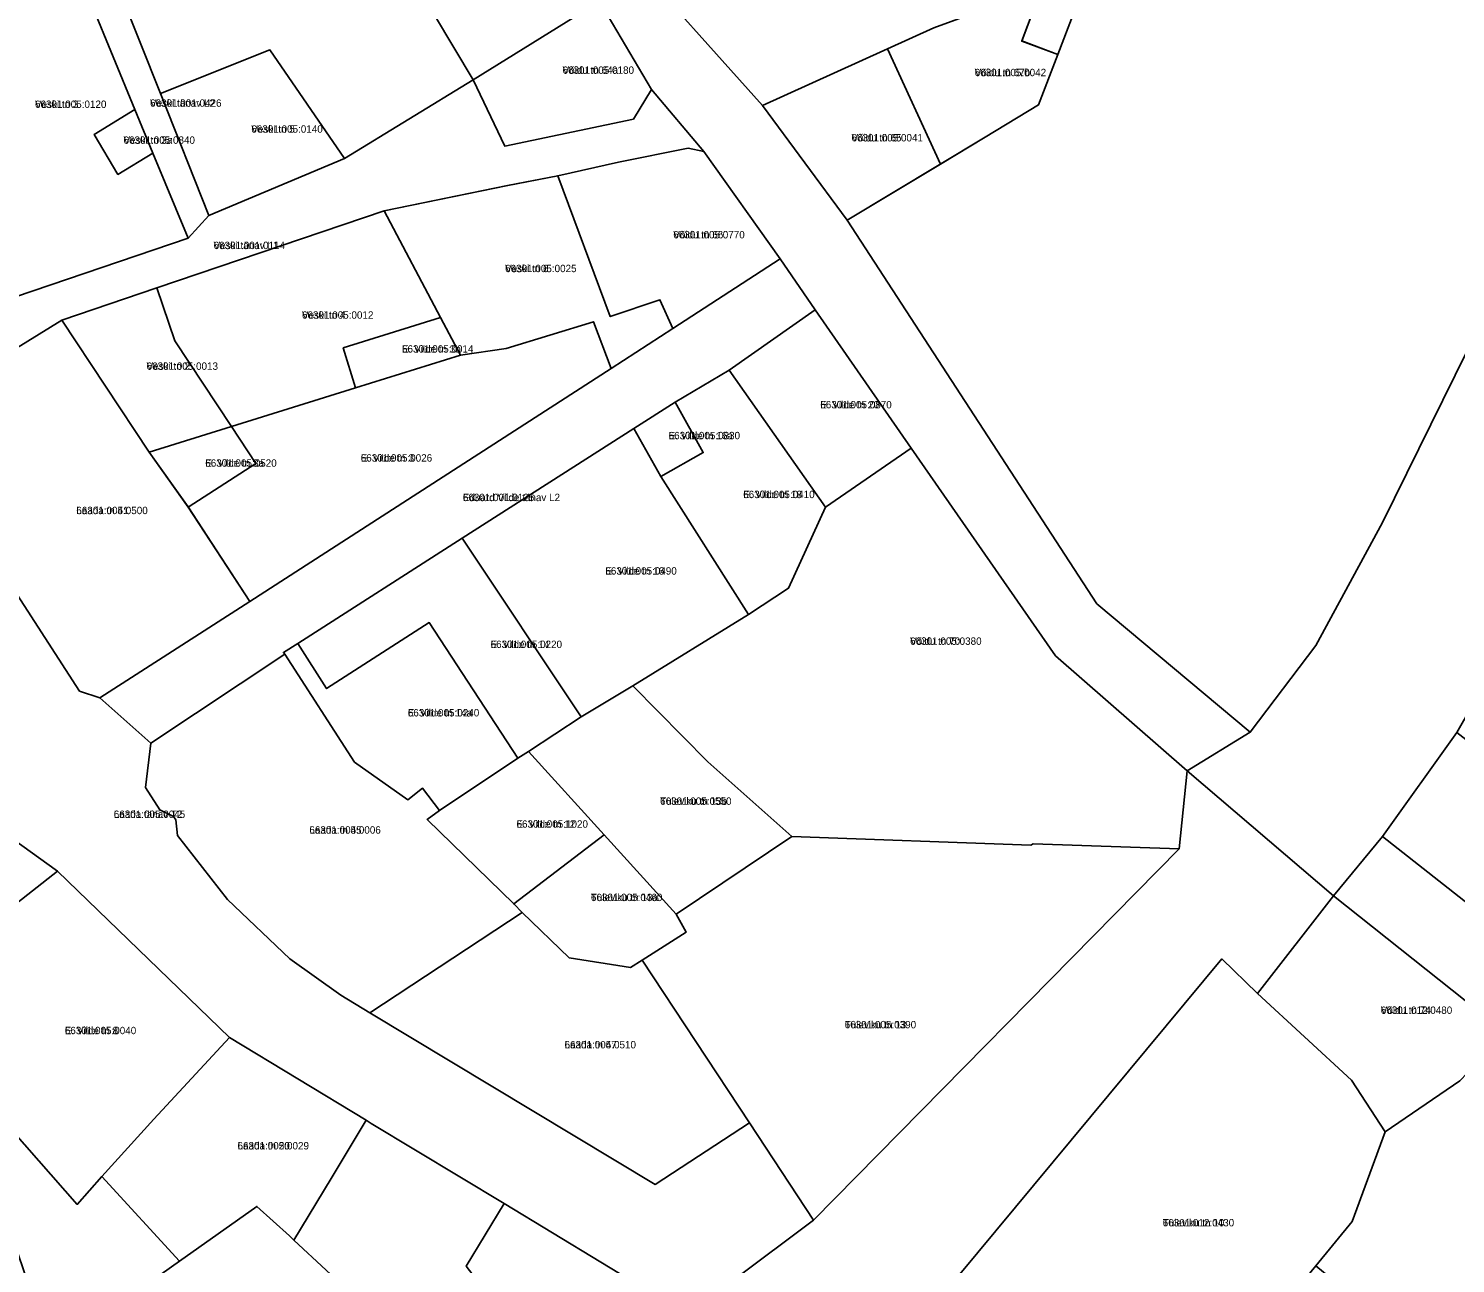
# Model space of a CAD drawing. Extents: x 632278 to 636344, y 6578401 to 6583362.
# Drawn here: x 634548.1 to 634837.7, y 6581009.9 to 6581260.6 of the extents above; entities that cross this region are included whole.
import ezdxf

# ---------------------------------------------------------------- set-up
doc = ezdxf.new("R2010")
doc.units = 0
for name, color, linetype in [('L_AADRESS', 7, 'Continuous'), ('PIIR', 7, 'Continuous'), ('TUNNUS', 7, 'Continuous')]:
    doc.layers.add(name, color=color, linetype=linetype)

msp = doc.modelspace()

# ---------------------------------------------------------------- linework, layer by layer
at = {"layer": 'PIIR'}
for points in [[(634574.9, 6581247.39), (634566.68, 6581268.15), (634584.63, 6581276.42), (634564.67, 6581308.89), (634593.05, 6581325.91), (634595.46, 6581321.77), (634606.06, 6581303.55), (634622.45, 6581276.78), (634638.34, 6581250.11), (634612.24, 6581234.15), (634597.13, 6581256.23)], [(634668.51, 6581276.9), (634704.2, 6581289.11), (634755.76, 6581305.99), (634773, 6581312.97), (634795.84, 6581322.71), (634798.08, 6581319.59), (634779.73, 6581311.78), (634760.78, 6581304.51), (634751.7, 6581296.87), (634756.06, 6581281.16), (634766.34, 6581281.97), (634767.88, 6581273.86), (634731.89, 6581260.67), (634697.11, 6581244.94)], [(634622.45, 6581276.78), (634651.83, 6581286.57), (634663.99, 6581266.03), (634638.34, 6581250.11)], [(634538.44, 6581203.74), (634518.37, 6581263.36), (634553.36, 6581283.68), (634560.88, 6581265.49), (634569.72, 6581244.11), (634561.46, 6581239.08), (634566.28, 6581230.93), (634573.36, 6581235.28), (634580.51, 6581218.01)], [(634722.43, 6581256.43), (634731.85, 6581260.7), (634753.73, 6581268.73), (634752.99, 6581266.7), (634749.71, 6581258.04), (634757.02, 6581255.3), (634753.1, 6581245.04), (634742.28, 6581238.5), (634733.22, 6581233.04)], [(634560.88, 6581265.49), (634566.68, 6581268.15), (634574.9, 6581247.39), (634584.71, 6581222.59), (634580.51, 6581218.01), (634573.36, 6581235.28), (634569.72, 6581244.11)], [(634670.88, 6581242.13), (634644.79, 6581236.69), (634638.34, 6581250.11), (634663.99, 6581266.03), (634674.56, 6581248.21)], [(634752.99, 6581266.7), (634760.32, 6581263.95), (634757.02, 6581255.3), (634749.71, 6581257.96)], [(634584.71, 6581222.59), (634574.9, 6581247.39), (634597.13, 6581256.23), (634612.24, 6581234.15)], [(634697.09, 6581244.95), (634722.43, 6581256.43), (634733.22, 6581233.04), (634714.31, 6581221.64)], [(634511.36, 6581194.15), (634538.44, 6581203.74), (634580.51, 6581218.01), (634584.71, 6581222.59), (634612.24, 6581234.15), (634638.34, 6581250.11), (634644.79, 6581236.69), (634670.88, 6581242.13), (634674.56, 6581248.21), (634685.17, 6581235.58), (634682.03, 6581236.25), (634667.86, 6581233.4), (634655.55, 6581230.66), (634645.38, 6581228.72), (634620.28, 6581223.53), (634574.17, 6581207.92), (634554.86, 6581201.37), (634522.63, 6581181.47)], [(634561.46, 6581239.08), (634569.72, 6581244.11), (634573.36, 6581235.28), (634566.28, 6581230.93)], [(634666.18, 6581202.11), (634655.55, 6581230.66), (634667.86, 6581233.4), (634682.03, 6581236.25), (634685.17, 6581235.58), (634700.66, 6581213.79), (634678.9, 6581199.67), (634676.26, 6581205.52)], [(634655.55, 6581230.66), (634666.18, 6581202.11), (634676.26, 6581205.52), (634678.9, 6581199.67), (634666.37, 6581191.55), (634662.77, 6581201.06), (634645.05, 6581195.59), (634635.83, 6581194.28), (634631.77, 6581201.91), (634620.28, 6581223.53), (634645.37, 6581228.72)], [(634574.17, 6581207.91), (634620.28, 6581223.53), (634631.77, 6581201.91), (634611.99, 6581195.75), (634614.51, 6581187.64), (634589.31, 6581179.79), (634577.82, 6581197.19)], [(634562.6, 6581124.73), (634593.03, 6581144.26), (634666.37, 6581191.55), (634678.9, 6581199.67), (634700.66, 6581213.79), (634707.78, 6581203.49), (634690.35, 6581191.22), (634679.4, 6581184.7), (634671, 6581179.38), (634636.17, 6581157.15), (634602.81, 6581135.76), (634599.86, 6581133.95), (634600.12, 6581133.55), (634572.96, 6581115.49)], [(634554.86, 6581201.37), (634574.17, 6581207.91), (634577.82, 6581197.19), (634589.31, 6581179.79), (634572.61, 6581174.58)], [(634611.99, 6581195.75), (634631.77, 6581201.91), (634635.83, 6581194.28), (634614.51, 6581187.64)], [(634690.35, 6581191.22), (634707.78, 6581203.49), (634727.29, 6581175.4), (634709.89, 6581163.43)], [(634522.63, 6581181.47), (634554.86, 6581201.37), (634572.61, 6581174.58), (634580.53, 6581163.46), (634593.03, 6581144.26), (634562.6, 6581124.73), (634558.5, 6581126.08)], [(634662.77, 6581201.06), (634666.37, 6581191.55), (634593.03, 6581144.26), (634580.54, 6581163.45), (634594.29, 6581172.27), (634589.31, 6581179.79), (634614.51, 6581187.64), (634635.83, 6581194.28), (634645.05, 6581195.59)], [(634676.46, 6581169.67), (634685.08, 6581174.49), (634679.4, 6581184.7), (634690.35, 6581191.22), (634709.89, 6581163.43), (634702.39, 6581146.97), (634694.22, 6581141.64)], [(634671, 6581179.38), (634679.4, 6581184.7), (634685.08, 6581174.49), (634676.46, 6581169.67)], [(634572.61, 6581174.58), (634589.31, 6581179.79), (634594.29, 6581172.27), (634580.54, 6581163.45)], [(634636.17, 6581157.15), (634671, 6581179.38), (634676.46, 6581169.67), (634694.22, 6581141.64), (634670.81, 6581127.16), (634660.28, 6581120.84)], [(634727.29, 6581175.4), (634756.56, 6581133.25), (634783.31, 6581109.93), (634781.69, 6581094.11), (634752.06, 6581095.06), (634751.54, 6581094.85), (634703.02, 6581096.57), (634686.02, 6581111.73), (634670.81, 6581127.16), (634694.22, 6581141.64), (634702.39, 6581146.97), (634709.89, 6581163.43)], [(634649.59, 6581113.83), (634647.41, 6581112.51), (634629.46, 6581139.98), (634608.61, 6581126.59), (634602.81, 6581135.76), (634636.17, 6581157.15), (634660.28, 6581120.84)], [(634614.32, 6581111.67), (634600.12, 6581133.55), (634599.86, 6581133.95), (634602.81, 6581135.76), (634608.61, 6581126.59), (634629.46, 6581139.98), (634647.41, 6581112.51), (634631.52, 6581101.89), (634628.11, 6581106.38), (634625.14, 6581104.03)], [(634572.96, 6581115.49), (634600.12, 6581133.55), (634614.32, 6581111.67), (634625.14, 6581104.03), (634628.11, 6581106.38), (634631.52, 6581101.89), (634629.01, 6581100), (634646.61, 6581082.89), (634648.31, 6581081.17), (634617.41, 6581060.76), (634611.53, 6581064.36), (634601.18, 6581071.74), (634588.53, 6581083.81), (634578.36, 6581096.81), (634578, 6581099.98), (634577.54, 6581100.62), (634574.81, 6581101.96), (634571.9, 6581106.52)], [(634649.59, 6581113.83), (634660.28, 6581120.84), (634670.81, 6581127.16), (634686.02, 6581111.73), (634703.02, 6581096.57), (634679.6, 6581080.81), (634664.94, 6581096.94)], [(634838.01, 6581117.66), (634849.52, 6581108.77), (634861.66, 6581102.77), (634873.56, 6581094.5), (634855, 6581071.36), (634822.93, 6581096.59)], [(634629.01, 6581100), (634631.52, 6581101.89), (634647.41, 6581112.51), (634649.59, 6581113.83), (634664.94, 6581096.94), (634646.61, 6581082.89)], [(634383.52, 6581003.02), (634393.61, 6580993.77), (634418.63, 6580994.06), (634427.83, 6581002.64), (634428.95, 6581001.54), (634439.54, 6581010.73), (634465.54, 6581032.93), (634479.89, 6581045.19), (634541.61, 6581098.39), (634554, 6581089.57), (634544.84, 6581082.29), (634522.08, 6581062.96), (634515.79, 6581057.74), (634486.43, 6581032.96), (634461.22, 6581011.77), (634436.2, 6580990.76), (634432.66, 6580988.17), (634427.34, 6580985.5), (634419.76, 6580983.73), (634387.16, 6580982.99)], [(634648.31, 6581081.17), (634646.61, 6581082.89), (634664.94, 6581096.94), (634679.6, 6581080.81), (634681.63, 6581077.18), (634672.65, 6581071.48), (634670.31, 6581070), (634657.86, 6581071.93)], [(634694.43, 6581038.46), (634672.65, 6581071.48), (634681.63, 6581077.18), (634679.6, 6581080.81), (634703.02, 6581096.57), (634751.54, 6581094.85), (634752.06, 6581095.06), (634781.69, 6581094.11), (634707.46, 6581018.72)], [(634526.35, 6581057.91), (634522.08, 6581062.96), (634544.84, 6581082.29), (634554, 6581089.57), (634588.9, 6581055.77), (634573.53, 6581039.2), (634563.03, 6581027.57), (634558.01, 6581021.92)], [(634797.56, 6581064.7), (634813.01, 6581084.53), (634847.95, 6581056.76), (634838.59, 6581047), (634823.5, 6581036.63), (634816.61, 6581047.12)], [(634648.31, 6581081.17), (634657.86, 6581071.93), (634670.31, 6581070), (634672.65, 6581071.48), (634694.43, 6581038.46), (634675.34, 6581025.98), (634617.41, 6581060.76)], [(634759.79, 6580993), (634751.74, 6581005.03), (634738.4, 6580991.36), (634733.61, 6580996.53), (634733.15, 6581002.97), (634790.34, 6581071.74), (634797.56, 6581064.7), (634816.61, 6581047.12), (634823.5, 6581036.63), (634816.8, 6581018.45), (634809.41, 6581009.48), (634793, 6580989.57), (634782.13, 6580974.46)], [(634515.79, 6581057.74), (634522.08, 6581062.96), (634526.35, 6581057.91), (634558.01, 6581021.92), (634563.03, 6581027.57), (634578.76, 6581010.38), (634560.35, 6580997.32), (634575.99, 6580976.83), (634604.11, 6580940.13), (634600.83, 6580937.71), (634563.93, 6580986.03), (634547.42, 6581007.65), (634538.39, 6581034.25)], [(634831.74, 6580991), (634809.41, 6581009.48), (634816.8, 6581018.45), (634823.5, 6581036.63), (634838.59, 6581047), (634847.95, 6581056.76), (634903.28, 6581012.64), (634850.41, 6580976.85)], [(634588.9, 6581055.77), (634616.67, 6581039.01), (634609.54, 6581027.18), (634602, 6581014.69), (634601.09, 6581015.56), (634594.49, 6581021.49), (634578.76, 6581010.38), (634563.03, 6581027.57), (634573.53, 6581039.2)], [(634616.67, 6581039.01), (634617.7, 6581038.36), (634644.69, 6581022.07), (634636.92, 6581009.38), (634658.35, 6580981.56), (634646.91, 6580972.75), (634624.15, 6580955.5), (634598.46, 6580987.41), (634615.08, 6581002.5), (634602, 6581014.69), (634609.54, 6581027.18)], [(634644.69, 6581022.07), (634674.12, 6581004.24), (634675.35, 6580994.7), (634658.35, 6580981.56), (634636.92, 6581009.38)], [(634560.35, 6580997.32), (634578.76, 6581010.38), (634594.49, 6581021.49), (634601.09, 6581015.56), (634602, 6581014.69), (634615.08, 6581002.5), (634598.46, 6580987.41), (634595.11, 6580991.55), (634575.99, 6580976.83)]]:
    msp.add_lwpolyline(points, close=True, dxfattribs=at)
for points in [[(634668.51, 6581276.9), (634697.09, 6581244.95), (634714.31, 6581221.64), (634764.96, 6581143.81), (634796.07, 6581117.73), (634783.31, 6581109.93), (634756.56, 6581133.25), (634727.29, 6581175.4), (634707.78, 6581203.49), (634700.66, 6581213.79), (634685.17, 6581235.58), (634674.56, 6581248.21), (634663.99, 6581266.03)], [(634918.34, 6581271.91), (634893.28, 6581244.04), (634890.04, 6581239.13), (634891.17, 6581216.96), (634886.85, 6581206.58), (634877.61, 6581195.05), (634871.35, 6581180.44), (634860.3, 6581156.51), (634838.01, 6581117.66), (634822.93, 6581096.59), (634813.01, 6581084.53), (634783.31, 6581109.93), (634796.07, 6581117.73), (634809.38, 6581135.31), (634822.93, 6581160.31), (634840.08, 6581195.15), (634865.69, 6581262.77)], [(634865.69, 6581262.77), (634840.08, 6581195.15), (634822.93, 6581160.31), (634809.38, 6581135.31), (634796.07, 6581117.73), (634764.96, 6581143.81), (634714.31, 6581221.64), (634742.28, 6581238.5), (634753.1, 6581245.04), (634757.02, 6581255.3), (634760.32, 6581263.95)], [(634522.63, 6581181.47), (634558.5, 6581126.08), (634562.6, 6581124.73), (634572.96, 6581115.49), (634571.9, 6581106.52), (634574.81, 6581101.96), (634577.54, 6581100.62), (634578, 6581099.98), (634578.36, 6581096.81), (634588.53, 6581083.81), (634601.18, 6581071.74), (634611.53, 6581064.36), (634617.41, 6581060.76), (634675.34, 6581025.98), (634694.43, 6581038.46), (634707.46, 6581018.72), (634675.35, 6580994.7), (634674.12, 6581004.24), (634644.69, 6581022.07), (634617.7, 6581038.36), (634616.67, 6581039.01), (634588.9, 6581055.77), (634554, 6581089.57), (634541.61, 6581098.39)], [(634675.35, 6580994.7), (634707.46, 6581018.72), (634781.69, 6581094.11), (634783.31, 6581109.93), (634813.01, 6581084.53), (634797.56, 6581064.7), (634790.34, 6581071.74), (634733.15, 6581002.97)], [(634847.95, 6581056.76), (634813.01, 6581084.53), (634822.93, 6581096.59), (634855, 6581071.36)]]:
    msp.add_lwpolyline(points, dxfattribs=at)

# ---------------------------------------------------------------- texts
at = {"layer": 'L_AADRESS'}
for s, p in [('Võidu tn 64a', (634656.52, 6581251.36)), ('Võidu tn 67b', (634740.16, 6581250.88)), ('Veski tn 3', (634549.44, 6581244.44)), ('Veski tänav L2', (634572.8, 6581244.68)), ('Veski tn 5', (634593.35, 6581239.41)), ('Võidu tn 65', (634715.16, 6581237.64)), ('Veski tn 3a', (634567.41, 6581237.16)), ('Võidu tn 66', (634678.99, 6581217.96)), ('Veski tänav L1', (634585.69, 6581215.79)), ('Veski tn 6', (634644.86, 6581211.11)), ('Veski tn 4', (634603.63, 6581201.66)), ('E. Vilde tn 3b', (634623.93, 6581194.78)), ('Veski tn 2', (634572.09, 6581191.29)), ('E. Vilde tn 20', (634708.82, 6581183.47)), ('E. Vilde tn 16a', (634678.04, 6581177.2)), ('E. Vilde tn 3a', (634584, 6581171.62)), ('E. Vilde tn 3', (634615.55, 6581172.66)), ('E. Vilde tn 18', (634693.18, 6581165.25)), ('Eduard Vilde tänav L2', (634636.27, 6581164.64)), ('Laada tn 41', (634557.83, 6581162)), ('E. Vilde tn 16', (634665.2, 6581149.73)), ('E. Vilde tn 14', (634641.91, 6581134.83)), ('Võidu tn 70', (634727.06, 6581135.48)), ('E. Vilde tn 14a', (634625.11, 6581120.94)), ('Tuleviku tn 13b', (634676.31, 6581103.01)), ('Laada tänav T2', (634565.43, 6581100.35)), ('Laada tn 45', (634605.13, 6581097.16)), ('E. Vilde tn 12', (634647.17, 6581098.36)), ('Tuleviku tn 13a', (634662.27, 6581083.47)), ('Võidu tn 74', (634822.58, 6581060.58)), ('E. Vilde tn 8', (634555.49, 6581056.46)), ('Tuleviku tn 13', (634713.78, 6581057.65)), ('Laada tn 47', (634656.92, 6581053.58)), ('Laada tn 20', (634590.55, 6581033.07)), ('Tuleviku tn 10', (634778.32, 6581017.45))]:
    msp.add_text(s, height=1.5, dxfattribs=at).set_placement(p)
at = {"layer": 'TUNNUS'}
for s, p in [('66301:005:0180', (634656.52, 6581251.36)), ('66301:005:0042', (634740.16, 6581250.88)), ('66301:005:0120', (634549.44, 6581244.44)), ('66301:001:0426', (634572.8, 6581244.68)), ('66301:005:0140', (634593.35, 6581239.41)), ('66301:005:0840', (634567.41, 6581237.16)), ('66301:005:0041', (634715.16, 6581237.64)), ('66301:005:0770', (634678.99, 6581217.96)), ('66301:001:0114', (634585.69, 6581215.79)), ('66301:005:0025', (634644.86, 6581211.11)), ('66301:005:0012', (634603.63, 6581201.66)), ('66301:005:0014', (634623.93, 6581194.78)), ('66301:005:0013', (634572.09, 6581191.29)), ('66301:005:0870', (634708.82, 6581183.47)), ('66301:005:0830', (634678.04, 6581177.2)), ('66301:005:0520', (634584, 6581171.62)), ('66301:005:0026', (634615.55, 6581172.66)), ('66301:001:0125', (634636.27, 6581164.64)), ('66301:005:0410', (634693.18, 6581165.25)), ('66301:005:0500', (634557.83, 6581162)), ('66301:005:0490', (634665.2, 6581149.73)), ('66301:005:0220', (634641.91, 6581134.83)), ('66301:005:0380', (634727.06, 6581135.48)), ('66301:005:0240', (634625.11, 6581120.94)), ('66301:005:0550', (634676.31, 6581103.01)), ('66301:005:0045', (634565.43, 6581100.35)), ('66301:005:0006', (634605.13, 6581097.16)), ('66301:005:1020', (634647.17, 6581098.36)), ('66301:005:0460', (634662.27, 6581083.47)), ('66301:012:0480', (634822.58, 6581060.58)), ('66301:005:0040', (634555.49, 6581056.46)), ('66301:005:0390', (634713.78, 6581057.65)), ('66301:005:0510', (634656.92, 6581053.58)), ('66301:005:0029', (634590.55, 6581033.07)), ('66301:012:0430', (634778.32, 6581017.45))]:
    msp.add_text(s, height=1.5, dxfattribs=at).set_placement(p)

doc.saveas('drawing.dxf')
